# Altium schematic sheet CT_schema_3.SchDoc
size 398 x 262 mm
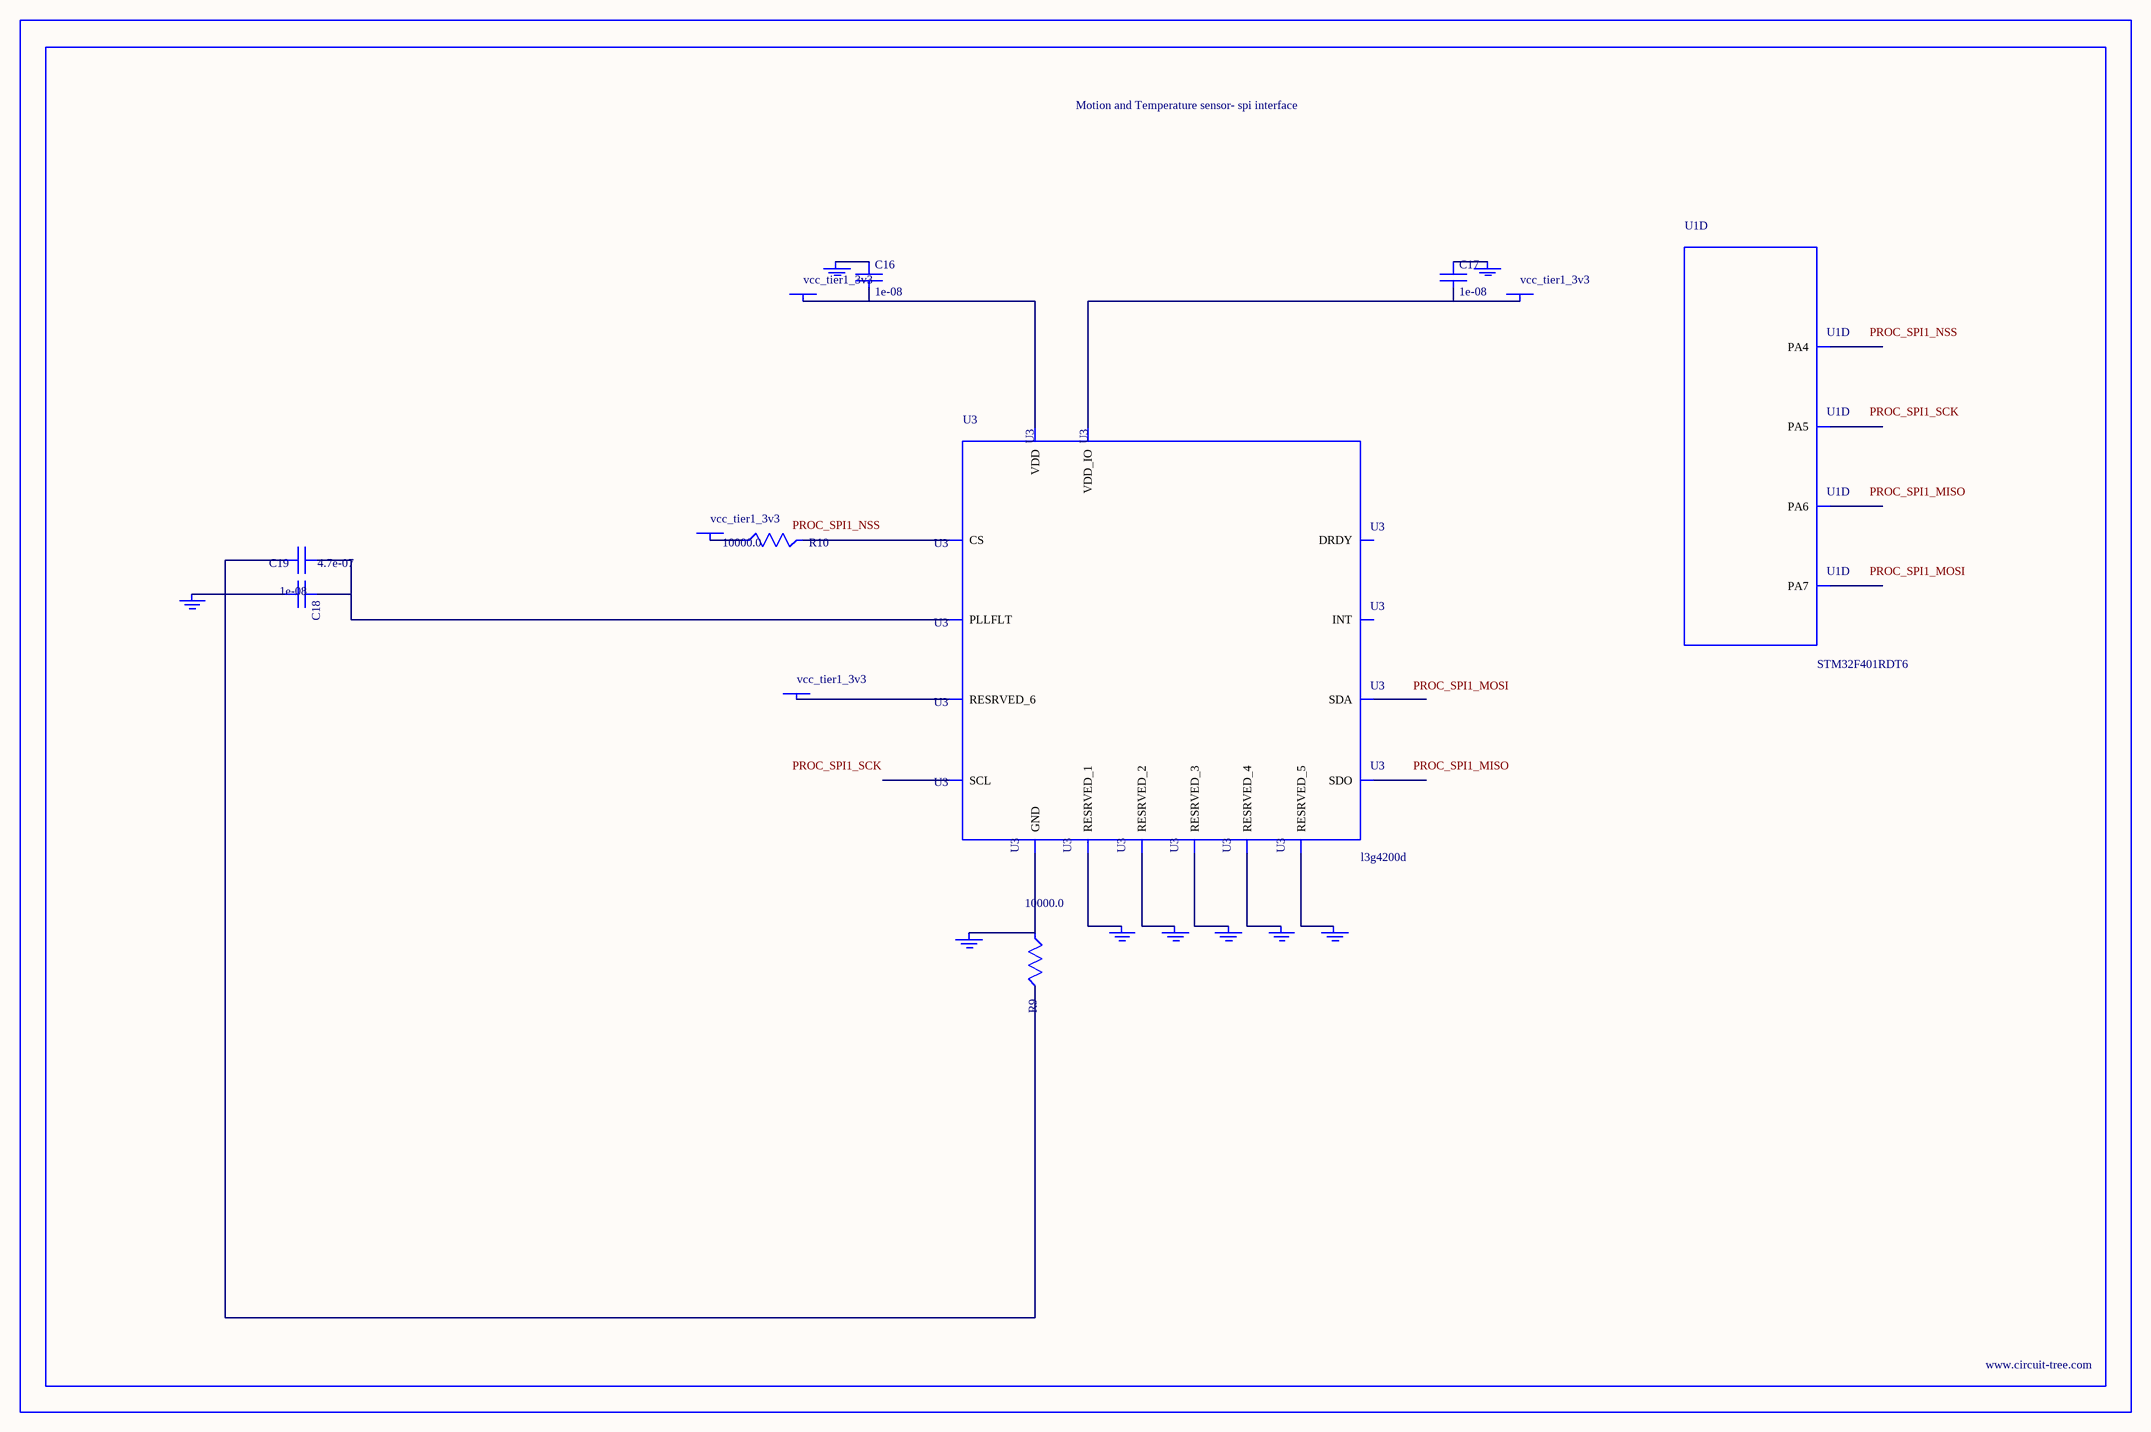
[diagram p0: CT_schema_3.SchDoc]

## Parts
BORDER2  (no value)
C16  1e-08  [C0402]
C17  1e-08  [C0402]
C18  1e-08  [C0402]
C19  4.7e-07  [C0603]
GND_INSTANCE_2_0  (no value)
GND_INSTANCE_2_1  (no value)
GND_INSTANCE_2_2  (no value)
GND_INSTANCE_2_3  (no value)
GND_INSTANCE_2_4  (no value)
GND_INSTANCE_2_5  (no value)
GND_INSTANCE_2_6  (no value)
GND_INSTANCE_2_7  (no value)
GND_INSTANCE_2_8  (no value)
POWER_INSTANCE_2_0  vcc_tier1_3v3
POWER_INSTANCE_2_1  vcc_tier1_3v3
POWER_INSTANCE_2_2  vcc_tier1_3v3
POWER_INSTANCE_2_3  vcc_tier1_3v3
R9  10000.0  [R0603]
R10  10000.0  [R0603]
U1  STM32F401RDT6  [LQFP64]  (part D of 7)
U3  l3g4200d  [LGA-16]

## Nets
NetC16_1: C16.1 GND_INSTANCE_2_8.0(GND)
NetC16_2: C16.2 POWER_INSTANCE_2_3.0(PWR) U3.16(VDD)
NetC17_1: C17.1 GND_INSTANCE_2_0.0(GND)
NetC17_2: C17.2 POWER_INSTANCE_2_0.0(PWR) U3.1(VDD_IO)
NetC18_1: C18.1 C19.1 U3.14(PLLFLT)
NetC18_2: C18.2 C19.2 GND_INSTANCE_2_7.0(GND) R9.2
NetGND_INSTANCE_2_1_0: GND_INSTANCE_2_1.0(GND) U3.8(RESRVED_1)
NetGND_INSTANCE_2_2_0: GND_INSTANCE_2_2.0(GND) U3.9(RESRVED_2)
NetGND_INSTANCE_2_3_0: GND_INSTANCE_2_3.0(GND) U3.10(RESRVED_3)
NetGND_INSTANCE_2_4_0: GND_INSTANCE_2_4.0(GND) U3.11(RESRVED_4)
NetGND_INSTANCE_2_5_0: GND_INSTANCE_2_5.0(GND) U3.12(RESRVED_5)
NetGND_INSTANCE_2_6_0: GND_INSTANCE_2_6.0(GND) R9.1 U3.13(GND)
NetPOWER_INSTANCE_2_1_0: POWER_INSTANCE_2_1.0(PWR) R10.1
NetPOWER_INSTANCE_2_2_0: POWER_INSTANCE_2_2.0(PWR) U3.15(RESRVED_6)
NetR10_2: R10.2 U3.5(CS)

Not connected (* = marked no-connect by the designer): U1 20(PA4) 21(PA5) 22(PA6) 23(PA7); U3 2(SCL) 3(SDA) 4(SDO) 6(DRDY) 7(INT)

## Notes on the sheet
- Labels drawn without touching a wire or pin: PROC_SPI1_MISO, PROC_SPI1_MOSI, PROC_SPI1_NSS, PROC_SPI1_SCK

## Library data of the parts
BORDER2 = BORDER_PAGE2
C16-C18 = C0402C103K3RAC
C19 = C0603C474K3RAC
GND_INSTANCE_2_0-GND_INSTANCE_2_8 = GND
POWER_INSTANCE_2_0-POWER_INSTANCE_2_3 = PWR
R9 R10 = RC0603JR-0710KL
